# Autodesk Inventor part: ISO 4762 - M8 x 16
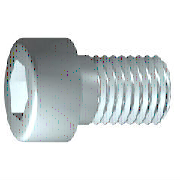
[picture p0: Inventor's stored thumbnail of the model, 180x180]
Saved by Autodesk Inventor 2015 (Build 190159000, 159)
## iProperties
Created: 2014-02
Part Number: ISO 4762 - M8 x 16
Material: Nerezová ocel 440C
Description: Šroub s válcovou hlavou s vnitřním šestihranem
Document SubType Name: Modeling
Standard: ISO 4762
Designer: navara
Standard Revision: Fourth edition 2004-03-01
Standards Organization: ISO
Language: cs-CZ
Size Designation: M8 x 16
Categories: <MemberInstance><Categories><Category DisplayName="Spojovací materiál" InternalName="e4da775c-781d-43d5-af7c-5136215cf5a6" Mnemonic="FSTN"><Category DisplayName
Density: 7.75 g/cm^3
Appearance: Pololeštěná
IsCustomPart: 0
Author: navara
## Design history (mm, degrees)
sketch "Náčrt1"
  geometry: L1 (-2, 0)-(16, 0); L2 (16, 0)-(16, 4); L3 (16, 4)-(3.125, 4); L4 (3.125, 4)-(2.358, 4); L5 (2.358, 4)-(0, 4); L6 (0, 4)-(0, 6.5); L7 (0, 6.5)-(-8, 6.5); L8 (-8, 6.5)-(-8, 3.464); L9 (-8, 3.464)-(-4, 3.464); L10 (-4, 3.464)-(-2, 0); L11 (-12.8, 0)-(20.8, 0) reference; L12 (0, -1.3)-(0, 7.8) reference; L13 (3.125, 4)-(0, 4)
  constraints: 22 end point, 6 parallel, 2 collinear, 2 perpendicular, 1 horizontal, 1 point on line
  dimensions: "d1" = 12.875 distance from line of L3.end L2 (= GEL); "d2" = 0.76691 distance of L4.end L3.end (computed from GAL); "d3" = 8 distance between parallel lines of L8 L6 (= KOH); "d4" = 4 distance of L8.end L9.end (= INTI); "d5" = 60 deg angle of L10 L1; "d6" = 8 diameter of L3 L1 (= GD); "d7" = 8 diameter of L5 L1 (= BDM); "d8" = 6.9282 diameter of L9 L1 (= 1.1547 x SW); "d9" = 13 diameter of L7 L1 (= KOD); "d26" = 16 distance between parallel lines of L12 L2 (= NLG)
revolve "Těleso" sketch "Náčrt1" stored, may be unused: angle "d10" = 90 deg
sketch "Náčrt2"
  geometry: L1 (0, -9.1)-(0, 9.1) reference; L2 (-9.1, 0)-(9.1, 0) reference; L3 (3.464, 0)-(1.732, -3); L4 (1.732, -3)-(-1.732, -3); L5 (-1.732, -3)-(-3.464, 0); L6 (-3.464, 0)-(-1.732, 3); L7 (-1.732, 3)-(1.732, 3); L8 (1.732, 3)-(3.464, 0); 2 further points
  constraints: 12 end point, 1 coincident, 1 horizontal alignment, 1 point on line, 12 other
extrude "Drážka" join sketch "Náčrt2" stored distance "d11" = 10; taper "d12" = 0 deg
workplane "Work Plane1"
fillet "Fillet2" dims "d30" = 0.1 (= R)
body "Solid1"
fillet "Zaoblení1" dims "d17" = 0.8 (= RR)
feature "Závit" dims "d13" = 12.875 (= GEL), "d14" = 0
chamfer "Zkosení1" distance "d15" = 0.76681 (= -0.5 x SPD + 0.5 x GD); stored, may be unused: second distance "d16" = 0.76681 (= GUL), angle "d27" = 45 deg
other parameters: "GD" = 8 [user parameter; used in 2 equation terms], "NLG" = 16 [user parameter; used in 1 equation term], "GEL" = 12.875 [user parameter; used in 2 equation terms], "KOD" = 13 [user parameter; used in 1 equation term], "KOH" = 8 [user parameter; used in 1 equation term], "INTI" = 4 [user parameter; used in 1 equation term], "GAL" = 0.76681 (= 0.61345 x PTC) [user parameter; used in 1 equation term], "GUL" = 0.76681 (= 0.61345 x PTC) [user parameter; used in 1 equation term], "BDM" = 8 (= NND) [user parameter; used in 1 equation term], "SW" = 6 [user parameter; used in 2 equation terms], "RR" = 0.8 [user parameter; used in 1 equation term], "SPD" = 6.46637 (= NND - 1.2269 x PTC) [user parameter; used in 1 equation term], "d19" = 0, "d28" = 0, "d29" = 0, "R" = 0.1 [user parameter; used in 1 equation term], "TOA" = 30 deg [user parameter], "GD1" = 6.46637 (= THREADDIA - 1.2269 x PTC) [user parameter], "THREADDIA" = 8 [user parameter; used in 1 equation term], "FAWI" = 45 deg [user parameter], "TPU" = 8 (computed from PTC) [user parameter], "PTC" = 1.25 [user parameter; used in 5 equation terms], "NND" = 8 [user parameter; used in 2 equation terms], "E0" = 6.93 (= 1.155 x SW) [user parameter]
